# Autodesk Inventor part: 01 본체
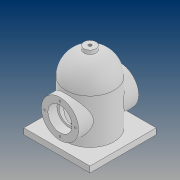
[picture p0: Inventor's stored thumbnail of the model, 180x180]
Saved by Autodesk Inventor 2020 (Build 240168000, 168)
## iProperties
Created: 2021-08
Part Number: 01 본체
Material: 일반
Document SubType Name: Modeling
Designer: PC312-
Density: 1 g/cm^3
Appearance: 기본값
Author: PC312-
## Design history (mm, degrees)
sketch "스케치1"
  geometry: C1 r 40 at (0, 0); 1 further point
  constraints: 1 centre point, 1 coincident
  dimensions: "d0" = 80 diameter of C1
extrude "돌출1" new body sketch "스케치1" distance "d1" = 124; taper "d2" = 0 deg
sketch "스케치2"
  geometry: 1 further point
fillet "모깎기1" dims "d3" = 40
feature "쉘1" dims "d4" = 8
sketch "스케치3"
  geometry: L1 (55, 55)-(-55, 55); L2 (-55, 55)-(-55, -55); L3 (-55, -55)-(55, -55); L4 (55, -55)-(55, 55); L5 (55, 55)-(-55, -55); L6 (-55, 55)-(55, -55); C1 r 40 at (0, 0) reference; 1 further point
  constraints: 12 end point, 2 midpoint, 2 parallel, 1 horizontal, 1 perpendicular
  dimensions: "d5" = 110 distance between parallel lines of L2 L4; "d6" = 110 distance between parallel lines of L3 L1
extrude "돌출2" join sketch "스케치3" distance "d7" = 10; taper "d8" = 0 deg
node "작업 평면1"
sketch "스케치4"
  geometry: L1 (55, 0)-(-55, 0) reference; C1 r 31 at (0, 48); 2 further points
  constraints: 1 centre point, 1 midpoint, 1 vertical alignment
  dimensions: "d10" = 62 diameter of C1; "d11" = 48 distance from line of C1.centre L1
extrude "돌출3" join sketch "스케치4" stored distance "d12" = 10; taper "d13" = 0 deg
sketch "스케치5"
  geometry: C1 r 20 at (0, 0); C2 r 31 at (0, 0) reference; 1 further point
  constraints: 1 centre point, 1 concentric
  dimensions: "d14" = 40 diameter of C1
extrude "돌출4" cut sketch "스케치5" distance "d15" = 15; taper "d16" = 0 deg
sketch "스케치6"
  geometry: C1 r 16.5 at (0, 0); C2 r 20 at (0, 0) reference; 1 further point
  constraints: 1 centre point, 1 concentric
  dimensions: "d17" = 33 diameter of C1
extrude "돌출5" cut sketch "스케치6" extent not by distance; stored distance "d18" = 15; taper "d19" = 0 deg
sketch "스케치7"
  geometry: L1 (55, -48)-(-55, -48) reference; C1 r 31 at (0, 0) reference; 3 further points
  constraints: 1 midpoint, 1 vertical alignment
  dimensions: "d20" = 25.5 distance of C1.centre point (0, 25.5)
hole "구멍1" sketch "스케치7" at (0, 25.5) diameter "d21" = 3.242; stored, may be unused: countersink angle "d25" = 90 deg, drill point angle "d27" = 118 deg; dims "d22" = 8, "d23" = 4, "d24" = 2, "d26" = 10
node "작업 평면2"
sketch "스케치8"
  geometry: C1 r 10 at (0, 0); 1 further point
  constraints: 1 centre point, 1 coincident
  dimensions: "d32" = 20 diameter of C1
extrude "돌출6" join sketch "스케치8" stored distance "d33" = 15; taper "d34" = 0 deg
sketch "스케치9"
  geometry: C1 r 10 at (0, 0) reference; 2 further points
  constraints: 1 coincident
hole "구멍2" sketch "스케치9" at (0, 0) diameter "d35" = 5.1881; stored, may be unused: countersink angle "d39" = 90 deg, drill point angle "d41" = 0 deg; dims "d36" = 12, "d37" = 4, "d38" = 2, "d40" = 70
node "솔리드1"
pattern_circular "원형 패턴1" dims angle "d29" = 360 deg
mirror "미러1"
feature "A9D066F2-1C7D-4E18-AEED-F7BC21143FA4" dims "d21" = 3.242, "d22" = 8, "d23" = 4, "d24" = 2, "d25" = 90 deg, "d26" = 10, "d27" = 118 deg
other parameters: "d31" = -129
